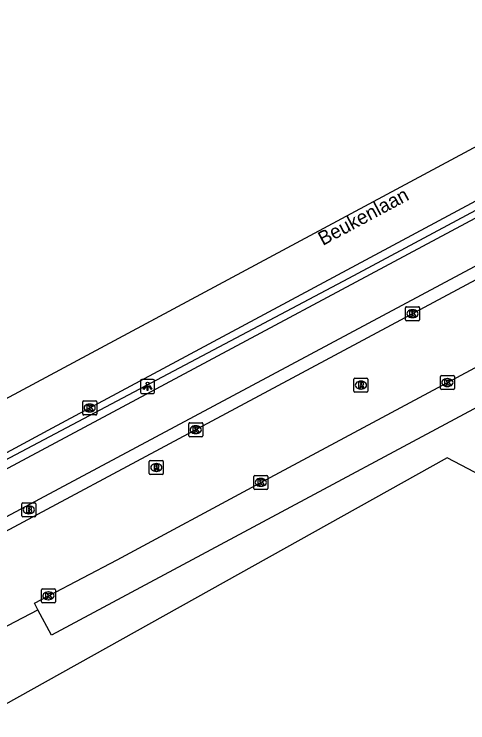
# Model space of a CAD drawing. Extents: x 159489 to 160304, y 383826 to 384530.
# Drawn here: x 159631.7 to 159664, y 384370.4 to 384420.9 of the extents above; entities that cross this region are included whole.
import ezdxf

# ---------------------------------------------------------------- set-up
doc = ezdxf.new("R2010")
doc.units = 0
for name, color, linetype in [('IMGEO_Berm_open', 7, 'Continuous'), ('IMGEO_Brandkraan', 7, 'Continuous'), ('IMGEO_Fietspad_gesloten', 7, 'Continuous'), ('IMGEO_Kolk', 7, 'Continuous'), ('IMGEO_Lichtpunt', 7, 'Continuous'), ('IMGEO_Openbare_ruimte_label', 7, 'Continuous'), ('IMGEO_Rijbaan_lokaal_gesloten', 7, 'Continuous'), ('IMGEO_Rijbaan_lokaal_open', 7, 'Continuous'), ('IMGEO_Rijbaan_regionaal_gesloten', 7, 'Continuous'), ('IMGEO_Rioolput', 7, 'Continuous'), ('IMGEO_Voetpad_open', 7, 'Continuous')]:
    doc.layers.add(name, color=color, linetype=linetype)

msp = doc.modelspace()

# ---------------------------------------------------------------- linework, layer by layer
at = {"layer": 'IMGEO_Berm_open'}
msp.add_lwpolyline([(159620.115, 384383.333), (159655.541, 384402.086), (159700.571, 384426.18), (159700.198, 384426.93)], dxfattribs=at)
at = {"layer": 'IMGEO_Brandkraan'}
for p, q in [((159632.302, 384386.07), (159633.154, 384386.07)), ((159632.227, 384385.144), (159632.227, 384385.996)), ((159632.715, 384385.85), (159632.74, 384385.85)), ((159633.228, 384385.996), (159633.228, 384385.144)), ((159633.154, 384385.07), (159632.302, 384385.07)), ((159632.738, 384385.29), (159632.713, 384385.29))]:
    msp.add_line(p, q, dxfattribs=at)
for points in [[(159632.302, 384386.07), (159633.154, 384386.07)], [(159632.227, 384385.144), (159632.227, 384385.996)], [(159632.575, 384385.77), (159632.575, 384385.37), (159632.788, 384385.37)], [(159632.806, 384385.77), (159632.575, 384385.77)], [(159632.754, 384385.689), (159632.7, 384385.689), (159632.7, 384385.613)], [(159632.7, 384385.613), (159632.753, 384385.613)], [(159632.762, 384385.537), (159632.7, 384385.537), (159632.7, 384385.456)], [(159633.228, 384385.996), (159633.228, 384385.144)], [(159633.154, 384385.07), (159632.302, 384385.07)], [(159632.7, 384385.456), (159632.762, 384385.456)]]:
    msp.add_lwpolyline(points, dxfattribs=at)
for centre, radius, start, end in [((159632.304, 384385.994), 0.0765, 91.552, 178.448), ((159632.304, 384385.994), 0.0765, 91.552, 178.448), ((159633.152, 384385.994), 0.0765, 1.552, 88.448), ((159633.152, 384385.994), 0.0765, 1.552, 88.448), ((159632.755, 384385.651), 0.0379, 267.8285, 90.9355), ((159632.763, 384385.496), 0.0404, 269.8759, 90.5077), ((159632.81, 384385.625), 0.145, 59.4692, 91.5367), ((159632.835, 384385.672), 0.0922, 285.5137, 58.1501), ((159632.84, 384385.48), 0.105, 301.3115, 78.989), ((159632.304, 384385.146), 0.0765, 181.552, 268.448), ((159632.304, 384385.146), 0.0765, 181.552, 268.448), ((159632.794, 384385.621), 0.251, 268.6676, 293.5347), ((159633.152, 384385.146), 0.0765, 271.552, 358.448), ((159633.152, 384385.146), 0.0765, 271.552, 358.448)]:
    msp.add_arc(centre, radius, start, end, dxfattribs=at)
for centre, major_axis, ratio, start_param, end_param in [((159632.714, 384385.57), (-0.387, 0.002), 0.722429, 4.712389, 7.853982), ((159632.739, 384385.57), (-0.39, 0.002), 0.717154, 1.570796, 4.712389)]:
    msp.add_ellipse(centre, major_axis=major_axis, ratio=ratio, start_param=start_param, end_param=end_param, dxfattribs=at)
at = {"layer": 'IMGEO_Fietspad_gesloten'}
for points in [[(159700.906, 384425.794), (159682.221, 384415.781), (159622.046, 384383.628), (159620.424, 384382.758)], [(159562.194, 384348.219), (159572.535, 384353.778), (159693.459, 384418.367)]]:
    msp.add_lwpolyline(points, dxfattribs=at)
at = {"layer": 'IMGEO_Kolk'}
for p, q in [((159659.584, 384399.116), (159659.584, 384399.968)), ((159659.659, 384400.042), (159660.511, 384400.042)), ((159660.072, 384399.822), (159660.097, 384399.822)), ((159660.585, 384399.968), (159660.585, 384399.116)), ((159660.095, 384399.262), (159660.07, 384399.262)), ((159660.511, 384399.042), (159659.659, 384399.042)), ((159662.148, 384395.136), (159663, 384395.136)), ((159662.073, 384394.21), (159662.073, 384395.062)), ((159662.561, 384394.916), (159662.586, 384394.916)), ((159663.074, 384395.062), (159663.074, 384394.21)), ((159663, 384394.136), (159662.148, 384394.136)), ((159662.584, 384394.356), (159662.559, 384394.356)), ((159636.569, 384392.399), (159636.569, 384393.251)), ((159636.644, 384393.325), (159637.496, 384393.325)), ((159637.057, 384393.105), (159637.082, 384393.105)), ((159637.57, 384393.251), (159637.57, 384392.399)), ((159637.496, 384392.325), (159636.644, 384392.325)), ((159637.08, 384392.545), (159637.055, 384392.545)), ((159644.128, 384390.851), (159644.128, 384391.703)), ((159644.203, 384391.777), (159645.055, 384391.777)), ((159645.129, 384391.703), (159645.129, 384390.851)), ((159644.616, 384391.557), (159644.641, 384391.557)), ((159645.055, 384390.777), (159644.203, 384390.777)), ((159644.639, 384390.997), (159644.614, 384390.997)), ((159648.768, 384387.097), (159648.768, 384387.949)), ((159648.843, 384388.023), (159649.695, 384388.023)), ((159649.256, 384387.803), (159649.281, 384387.803)), ((159649.769, 384387.949), (159649.769, 384387.097)), ((159649.279, 384387.243), (159649.254, 384387.243)), ((159649.695, 384387.023), (159648.843, 384387.023)), ((159633.627, 384379.014), (159633.627, 384379.866)), ((159633.702, 384379.94), (159634.554, 384379.94)), ((159634.115, 384379.72), (159634.14, 384379.72)), ((159634.628, 384379.866), (159634.628, 384379.014)), ((159634.138, 384379.16), (159634.113, 384379.16)), ((159634.554, 384378.94), (159633.702, 384378.94))]:
    msp.add_line(p, q, dxfattribs=at)
for points in [[(159659.584, 384399.116), (159659.584, 384399.968)], [(159659.659, 384400.042), (159660.511, 384400.042)], [(159659.905, 384399.742), (159660.028, 384399.742), (159660.028, 384399.591), (159660.158, 384399.742), (159660.322, 384399.742), (159660.176, 384399.591), (159660.329, 384399.342), (159660.177, 384399.342), (159660.092, 384399.506), (159660.028, 384399.439), (159660.028, 384399.342), (159659.905, 384399.342), (159659.905, 384399.742)], [(159660.585, 384399.968), (159660.585, 384399.116)], [(159660.511, 384399.042), (159659.659, 384399.042)], [(159662.148, 384395.136), (159663, 384395.136)], [(159662.073, 384394.21), (159662.073, 384395.062)], [(159662.394, 384394.836), (159662.517, 384394.836), (159662.517, 384394.685), (159662.647, 384394.836), (159662.811, 384394.836), (159662.665, 384394.685), (159662.818, 384394.436), (159662.666, 384394.436), (159662.581, 384394.6), (159662.517, 384394.533), (159662.517, 384394.436), (159662.394, 384394.436), (159662.394, 384394.836)], [(159663.074, 384395.062), (159663.074, 384394.21)], [(159663, 384394.136), (159662.148, 384394.136)], [(159636.569, 384392.399), (159636.569, 384393.251)], [(159636.644, 384393.325), (159637.496, 384393.325)], [(159637.57, 384393.251), (159637.57, 384392.399)], [(159636.89, 384393.025), (159637.013, 384393.025), (159637.013, 384392.874), (159637.143, 384393.025), (159637.307, 384393.025), (159637.161, 384392.874), (159637.314, 384392.625), (159637.162, 384392.625), (159637.077, 384392.789), (159637.013, 384392.722), (159637.013, 384392.625), (159636.89, 384392.625), (159636.89, 384393.025)], [(159637.496, 384392.325), (159636.644, 384392.325)], [(159644.128, 384390.851), (159644.128, 384391.703)], [(159644.203, 384391.777), (159645.055, 384391.777)], [(159645.129, 384391.703), (159645.129, 384390.851)], [(159644.449, 384391.477), (159644.572, 384391.477), (159644.572, 384391.326), (159644.702, 384391.477), (159644.866, 384391.477), (159644.72, 384391.326), (159644.873, 384391.077), (159644.721, 384391.077), (159644.636, 384391.241), (159644.572, 384391.174), (159644.572, 384391.077), (159644.449, 384391.077), (159644.449, 384391.477)], [(159645.055, 384390.777), (159644.203, 384390.777)], [(159648.768, 384387.097), (159648.768, 384387.949)], [(159648.843, 384388.023), (159649.695, 384388.023)], [(159649.089, 384387.723), (159649.212, 384387.723), (159649.212, 384387.572), (159649.342, 384387.723), (159649.506, 384387.723), (159649.36, 384387.572), (159649.513, 384387.323), (159649.361, 384387.323), (159649.276, 384387.487), (159649.212, 384387.42), (159649.212, 384387.323), (159649.089, 384387.323), (159649.089, 384387.723)], [(159649.769, 384387.949), (159649.769, 384387.097)], [(159649.695, 384387.023), (159648.843, 384387.023)], [(159633.627, 384379.014), (159633.627, 384379.866)], [(159633.702, 384379.94), (159634.554, 384379.94)], [(159633.948, 384379.64), (159634.071, 384379.64), (159634.071, 384379.489), (159634.201, 384379.64), (159634.365, 384379.64), (159634.219, 384379.489), (159634.372, 384379.24), (159634.22, 384379.24), (159634.135, 384379.404), (159634.071, 384379.337), (159634.071, 384379.24), (159633.948, 384379.24), (159633.948, 384379.64)], [(159634.628, 384379.866), (159634.628, 384379.014)], [(159634.554, 384378.94), (159633.702, 384378.94)]]:
    msp.add_lwpolyline(points, dxfattribs=at)
for centre, start, end in [((159659.661, 384399.966), 91.552, 178.448), ((159659.661, 384399.966), 91.552, 178.448), ((159660.509, 384399.966), 1.552, 88.448), ((159660.509, 384399.966), 1.552, 88.448), ((159659.661, 384399.118), 181.552, 268.448), ((159659.661, 384399.118), 181.552, 268.448), ((159660.509, 384399.118), 271.552, 358.448), ((159660.509, 384399.118), 271.552, 358.448), ((159662.15, 384395.06), 91.552, 178.448), ((159662.15, 384395.06), 91.552, 178.448), ((159662.998, 384395.06), 1.552, 88.448), ((159662.998, 384395.06), 1.552, 88.448), ((159662.15, 384394.212), 181.552, 268.448), ((159662.15, 384394.212), 181.552, 268.448), ((159662.998, 384394.212), 271.552, 358.448), ((159662.998, 384394.212), 271.552, 358.448), ((159636.646, 384393.249), 91.552, 178.448), ((159636.646, 384393.249), 91.552, 178.448), ((159637.494, 384393.249), 1.552, 88.448), ((159637.494, 384393.249), 1.552, 88.448), ((159636.646, 384392.401), 181.552, 268.448), ((159636.646, 384392.401), 181.552, 268.448), ((159637.494, 384392.401), 271.552, 358.448), ((159637.494, 384392.401), 271.552, 358.448), ((159644.205, 384391.701), 91.552, 178.448), ((159644.205, 384391.701), 91.552, 178.448), ((159645.053, 384391.701), 1.552, 88.448), ((159645.053, 384391.701), 1.552, 88.448), ((159644.205, 384390.853), 181.552, 268.448), ((159644.205, 384390.853), 181.552, 268.448), ((159645.053, 384390.853), 271.552, 358.448), ((159645.053, 384390.853), 271.552, 358.448), ((159648.845, 384387.947), 91.552, 178.448), ((159648.845, 384387.947), 91.552, 178.448), ((159649.693, 384387.947), 1.552, 88.448), ((159649.693, 384387.947), 1.552, 88.448), ((159648.845, 384387.099), 181.552, 268.448), ((159648.845, 384387.099), 181.552, 268.448), ((159649.693, 384387.099), 271.552, 358.448), ((159649.693, 384387.099), 271.552, 358.448), ((159633.704, 384379.864), 91.552, 178.448), ((159633.704, 384379.864), 91.552, 178.448), ((159634.552, 384379.864), 1.552, 88.448), ((159634.552, 384379.864), 1.552, 88.448), ((159633.704, 384379.016), 181.552, 268.448), ((159633.704, 384379.016), 181.552, 268.448), ((159634.552, 384379.016), 271.552, 358.448), ((159634.552, 384379.016), 271.552, 358.448)]:
    msp.add_arc(centre, 0.0765, start, end, dxfattribs=at)
for centre, major_axis, ratio, start_param, end_param in [((159660.071, 384399.542), (-0.387, 0.002), 0.722429, 4.712389, 7.853982), ((159660.096, 384399.542), (-0.39, 0.002), 0.717154, 1.570796, 4.712389), ((159662.56, 384394.636), (-0.387, 0.002), 0.722429, 4.712389, 7.853982), ((159662.585, 384394.636), (-0.39, 0.002), 0.717154, 1.570796, 4.712389), ((159637.056, 384392.825), (-0.387, 0.002), 0.722429, 4.712389, 7.853982), ((159637.081, 384392.825), (-0.39, 0.002), 0.717154, 1.570796, 4.712389), ((159644.615, 384391.277), (-0.387, 0.002), 0.722429, 4.712389, 7.853982), ((159644.64, 384391.277), (-0.39, 0.002), 0.717154, 1.570796, 4.712389), ((159649.255, 384387.523), (-0.387, 0.002), 0.722429, 4.712389, 7.853982), ((159649.28, 384387.523), (-0.39, 0.002), 0.717154, 1.570796, 4.712389), ((159634.114, 384379.44), (-0.387, 0.002), 0.722429, 4.712389, 7.853982), ((159634.139, 384379.44), (-0.39, 0.002), 0.717154, 1.570796, 4.712389)]:
    msp.add_ellipse(centre, major_axis=major_axis, ratio=ratio, start_param=start_param, end_param=end_param, dxfattribs=at)
at = {"layer": 'IMGEO_Lichtpunt'}
for p, q in [((159640.7, 384394.769), (159640.7, 384393.962)), ((159640.7, 384394.769), (159640.7, 384393.962)), ((159641.602, 384394.864), (159640.794, 384394.864)), ((159641.602, 384394.864), (159640.794, 384394.864)), ((159641.696, 384393.962), (159641.696, 384394.769)), ((159641.696, 384393.962), (159641.696, 384394.769)), ((159640.794, 384393.868), (159641.602, 384393.868)), ((159640.794, 384393.868), (159641.602, 384393.868))]:
    msp.add_line(p, q, dxfattribs=at)
for points in [[(159641.074, 384394.433), (159641.113, 384394.405), (159640.925, 384394.143), (159640.887, 384394.17), (159641.074, 384394.433)], [(159641.176, 384394.385), (159641.223, 384394.385), (159641.223, 384394.063), (159641.176, 384394.063), (159641.176, 384394.385)], [(159641.286, 384394.405), (159641.324, 384394.432), (159641.511, 384394.17), (159641.472, 384394.142), (159641.286, 384394.405)]]:
    msp.add_lwpolyline(points, dxfattribs=at)
msp.add_circle((159641.199, 384394.567), 0.0994, dxfattribs=at)
for centre, start, end in [((159640.794, 384394.769), 90, 180), ((159640.794, 384394.769), 90, 180), ((159641.602, 384394.769), 0, 90), ((159641.602, 384394.769), 0, 90), ((159640.794, 384393.962), 180, 270), ((159640.794, 384393.962), 180, 270), ((159641.602, 384393.962), 270, 0), ((159641.602, 384393.962), 270, 360)]:
    msp.add_arc(centre, 0.0946, start, end, dxfattribs=at)
at = {"layer": 'IMGEO_Rijbaan_lokaal_gesloten'}
for points in [[(159693.863, 384417.603), (159580.529, 384357.003), (159566.867, 384349.736)], [(159633.379, 384378.441), (159633.124, 384378.917), (159634.128, 384379.44), (159639.03, 384381.993), (159649.269, 384387.523), (159662.574, 384394.636), (159677.343, 384402.539), (159677.726, 384402.756)], [(159611.421, 384366.774), (159627.528, 384375.393), (159633.379, 384378.441)]]:
    msp.add_lwpolyline(points, dxfattribs=at)
at = {"layer": 'IMGEO_Rijbaan_lokaal_open'}
msp.add_lwpolyline([(159712.165, 384382.809), (159710.4, 384383.814), (159709.804, 384384.582), (159708.791, 384386.232), (159707.09, 384388.078), (159705.538, 384389.14), (159699.558, 384392.447), (159689.963, 384397.545), (159688.197, 384398.149), (159685.752, 384398.573), (159683.758, 384398.622), (159682.319, 384398.41), (159680.259, 384397.773), (159677.113, 384396.112), (159669.384, 384391.81), (159667.587, 384390.432), (159665.498, 384387.718), (159662.566, 384389.265), (159617.084, 384363.924)], dxfattribs=at)
at = {"layer": 'IMGEO_Rijbaan_regionaal_gesloten'}
for points in [[(159618.33, 384386.664), (159630.055, 384392.935), (159696.891, 384428.803), (159718.831, 384440.572), (159756.87, 384460.87), (159792.184, 384479.496), (159799.29, 384483.122), (159806.379, 384486.798), (159827.767, 384497.696), (159874.847, 384521.573), (159884.805, 384526.627), (159885.682, 384527.066)], [(159619.966, 384383.61), (159634.421, 384391.406), (159668.244, 384409.54), (159699.377, 384426.484)]]:
    msp.add_lwpolyline(points, dxfattribs=at)
at = {"layer": 'IMGEO_Rioolput'}
for p, q in [((159655.91, 384394.029), (159655.91, 384394.881)), ((159655.985, 384394.955), (159656.837, 384394.955)), ((159656.398, 384394.735), (159656.423, 384394.735)), ((159656.911, 384394.881), (159656.911, 384394.029)), ((159656.421, 384394.175), (159656.396, 384394.175)), ((159656.837, 384393.955), (159655.985, 384393.955)), ((159641.393, 384389.083), (159642.245, 384389.083)), ((159641.318, 384388.157), (159641.318, 384389.009)), ((159641.806, 384388.863), (159641.831, 384388.863)), ((159642.319, 384389.009), (159642.319, 384388.157)), ((159642.245, 384388.083), (159641.393, 384388.083)), ((159641.829, 384388.303), (159641.804, 384388.303))]:
    msp.add_line(p, q, dxfattribs=at)
for points in [[(159655.91, 384394.029), (159655.91, 384394.881)], [(159655.985, 384394.955), (159656.837, 384394.955)], [(159656.499, 384394.653), (159656.247, 384394.655), (159656.247, 384394.255)], [(159656.911, 384394.881), (159656.911, 384394.029)], [(159656.247, 384394.255), (159656.371, 384394.255), (159656.371, 384394.417), (159656.382, 384394.417)], [(159656.425, 384394.574), (159656.371, 384394.574), (159656.371, 384394.493)], [(159656.371, 384394.493), (159656.423, 384394.493)], [(159656.429, 384394.388), (159656.5, 384394.255), (159656.64, 384394.255), (159656.575, 384394.381)], [(159656.837, 384393.955), (159655.985, 384393.955)], [(159641.393, 384389.083), (159642.245, 384389.083)], [(159641.318, 384388.157), (159641.318, 384389.009)], [(159641.907, 384388.781), (159641.655, 384388.783), (159641.655, 384388.383)], [(159641.655, 384388.383), (159641.779, 384388.383), (159641.779, 384388.545), (159641.79, 384388.545)], [(159641.833, 384388.702), (159641.779, 384388.702), (159641.779, 384388.621)], [(159641.779, 384388.621), (159641.831, 384388.621)], [(159642.319, 384389.009), (159642.319, 384388.157)], [(159642.245, 384388.083), (159641.393, 384388.083)], [(159641.837, 384388.516), (159641.908, 384388.383), (159642.048, 384388.383), (159641.983, 384388.509)]]:
    msp.add_lwpolyline(points, dxfattribs=at)
for centre, radius, start, end in [((159655.987, 384394.879), 0.0765, 91.552, 178.448), ((159655.987, 384394.879), 0.0765, 91.552, 178.448), ((159656.498, 384394.543), 0.109, 350.3612, 89.416), ((159656.835, 384394.879), 0.0765, 1.552, 88.448), ((159656.835, 384394.879), 0.0765, 1.552, 88.448), ((159656.381, 384394.364), 0.0533, 26.0293, 88.6989), ((159656.407, 384394.682), 0.19, 274.7715, 282.9687), ((159656.431, 384394.478), 0.0964, 77.0061, 93.1865), ((159656.445, 384394.535), 0.0378, 276.6634, 79.6772), ((159656.496, 384394.543), 0.112, 277.5842, 350.9817), ((159656.48, 384394.328), 0.108, 29.5134, 73.7905), ((159655.987, 384394.031), 0.0765, 181.552, 268.448), ((159655.987, 384394.031), 0.0765, 181.552, 268.448), ((159656.835, 384394.031), 0.0765, 271.552, 358.448), ((159656.835, 384394.031), 0.0765, 271.552, 358.448), ((159641.395, 384389.007), 0.0765, 91.552, 178.448), ((159641.395, 384389.007), 0.0765, 91.552, 178.448), ((159642.243, 384389.007), 0.0765, 1.552, 88.448), ((159642.243, 384389.007), 0.0765, 1.552, 88.448), ((159641.789, 384388.492), 0.0533, 26.0293, 88.6989), ((159641.815, 384388.81), 0.19, 274.7715, 282.9687), ((159641.839, 384388.606), 0.0964, 77.0061, 93.1865), ((159641.853, 384388.663), 0.0378, 276.6634, 79.6772), ((159641.906, 384388.671), 0.109, 350.3612, 89.416), ((159641.904, 384388.671), 0.112, 277.5842, 350.9817), ((159641.888, 384388.456), 0.108, 29.5134, 73.7905), ((159641.395, 384388.159), 0.0765, 181.552, 268.448), ((159641.395, 384388.159), 0.0765, 181.552, 268.448), ((159642.243, 384388.159), 0.0765, 271.552, 358.448), ((159642.243, 384388.159), 0.0765, 271.552, 358.448)]:
    msp.add_arc(centre, radius, start, end, dxfattribs=at)
for centre, major_axis, ratio, start_param, end_param in [((159656.397, 384394.455), (-0.387, 0.002), 0.722429, 4.712389, 7.853982), ((159656.422, 384394.455), (-0.39, 0.002), 0.717154, 1.570796, 4.712389), ((159641.805, 384388.583), (-0.387, 0.002), 0.722429, 4.712389, 7.853982), ((159641.83, 384388.583), (-0.39, 0.002), 0.717154, 1.570796, 4.712389)]:
    msp.add_ellipse(centre, major_axis=major_axis, ratio=ratio, start_param=start_param, end_param=end_param, dxfattribs=at)
at = {"layer": 'IMGEO_Voetpad_open'}
msp.add_lwpolyline([(159712.165, 384382.809), (159713.006, 384384.347), (159713.102, 384385.975), (159712.503, 384386.97), (159711.661, 384387.572), (159686.961, 384400.768), (159684.938, 384401.459), (159682.928, 384401.583), (159680.757, 384401.193), (159678.807, 384400.435), (159634.346, 384376.64), (159633.379, 384378.441)], dxfattribs=at)

# ---------------------------------------------------------------- texts
at = {"layer": 'IMGEO_Openbare_ruimte_label'}
msp.add_text('Beukenlaan', height=1, rotation=28.1028, dxfattribs=at).set_placement((159653.693, 384404.368))

doc.saveas('drawing.dxf')
